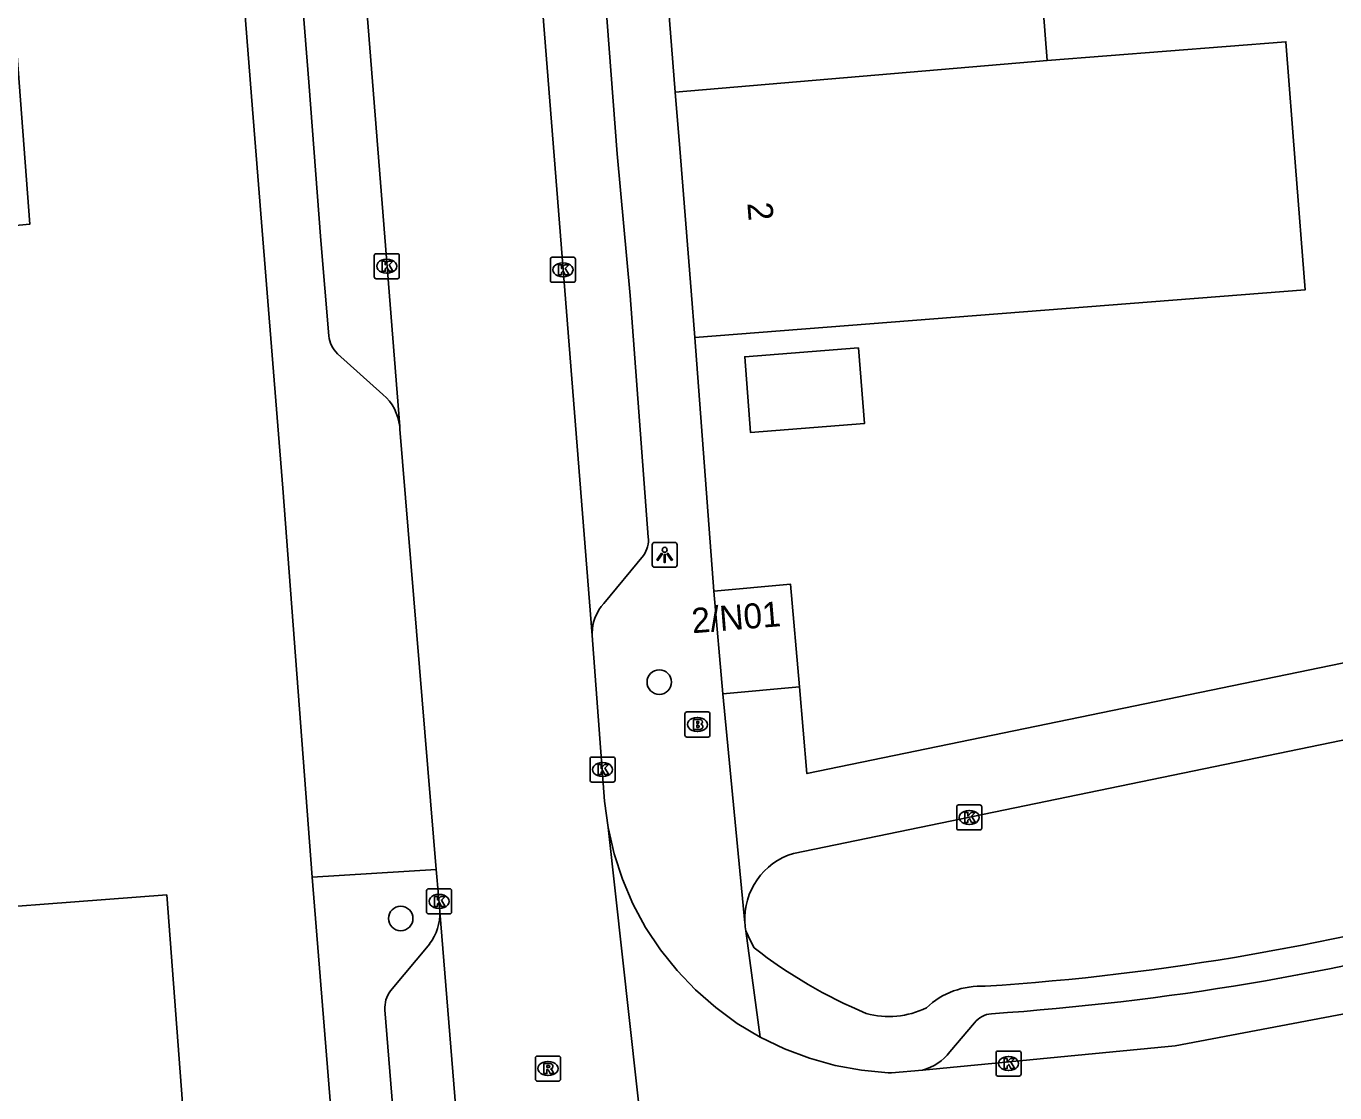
# Model space of a CAD drawing. Extents: x 157793 to 159380, y 380882 to 382313.
# Drawn here: x 158137.7 to 158189.9, y 381083.3 to 381125.9 of the extents above; entities that cross this region are included whole.
import ezdxf

# ---------------------------------------------------------------- set-up
doc = ezdxf.new("R2010")
doc.units = 0
for name, color, linetype in [('IMGEO_Boom', 7, 'Continuous'), ('IMGEO_Brandkraan', 7, 'Continuous'), ('IMGEO_Kolk', 7, 'Continuous'), ('IMGEO_Lichtpunt', 7, 'Continuous'), ('IMGEO_Muur', 7, 'Continuous'), ('IMGEO_Pand', 7, 'Continuous'), ('IMGEO_Pand_nummerreeks', 7, 'Continuous'), ('IMGEO_Rijbaan_lokaal_gesloten', 7, 'Continuous'), ('IMGEO_Rioolput', 7, 'Continuous'), ('IMGEO_Voetpad_open', 7, 'Continuous')]:
    doc.layers.add(name, color=color, linetype=linetype)

msp = doc.modelspace()

# ---------------------------------------------------------------- linework, layer by layer
at = {"layer": 'IMGEO_Boom'}
for centre in [(158162.949, 381099.665), (158152.619, 381090.221)]:
    msp.add_circle(centre, 0.489, dxfattribs=at)
at = {"layer": 'IMGEO_Brandkraan'}
for p, q in [((158163.973, 381097.545), (158163.973, 381098.397)), ((158164.048, 381098.471), (158164.9, 381098.471)), ((158164.461, 381098.251), (158164.486, 381098.251)), ((158164.974, 381098.397), (158164.974, 381097.545)), ((158164.484, 381097.691), (158164.459, 381097.691)), ((158164.9, 381097.471), (158164.048, 381097.471))]:
    msp.add_line(p, q, dxfattribs=at)
for points in [[(158163.973, 381097.545), (158163.973, 381098.397)], [(158164.048, 381098.471), (158164.9, 381098.471)], [(158164.321, 381098.171), (158164.321, 381097.771), (158164.534, 381097.771)], [(158164.552, 381098.171), (158164.321, 381098.171)], [(158164.5, 381098.09), (158164.446, 381098.09), (158164.446, 381098.014)], [(158164.446, 381098.014), (158164.499, 381098.014)], [(158164.974, 381098.397), (158164.974, 381097.545)], [(158164.508, 381097.938), (158164.446, 381097.938), (158164.446, 381097.857)], [(158164.446, 381097.857), (158164.508, 381097.857)], [(158164.9, 381097.471), (158164.048, 381097.471)]]:
    msp.add_lwpolyline(points, dxfattribs=at)
for centre, radius, start, end in [((158164.05, 381098.395), 0.0765, 91.552, 178.448), ((158164.05, 381098.395), 0.0765, 91.552, 178.448), ((158164.501, 381098.052), 0.0379, 267.8285, 90.9355), ((158164.556, 381098.026), 0.145, 59.4692, 91.5367), ((158164.581, 381098.073), 0.0922, 285.5137, 58.1501), ((158164.898, 381098.395), 0.0765, 1.552, 88.448), ((158164.898, 381098.395), 0.0765, 1.552, 88.448), ((158164.05, 381097.547), 0.0765, 181.552, 268.448), ((158164.05, 381097.547), 0.0765, 181.552, 268.448), ((158164.509, 381097.897), 0.0404, 269.8759, 90.5077), ((158164.54, 381098.022), 0.251, 268.6676, 293.5347), ((158164.586, 381097.881), 0.105, 301.3115, 78.989), ((158164.898, 381097.547), 0.0765, 271.552, 358.448), ((158164.898, 381097.547), 0.0765, 271.552, 358.448)]:
    msp.add_arc(centre, radius, start, end, dxfattribs=at)
for centre, major_axis, ratio, start_param, end_param in [((158164.46, 381097.971), (-0.387, 0.002), 0.722429, 4.712389, 7.853982), ((158164.485, 381097.971), (-0.39, 0.002), 0.717154, 1.570796, 4.712389)]:
    msp.add_ellipse(centre, major_axis=major_axis, ratio=ratio, start_param=start_param, end_param=end_param, dxfattribs=at)
at = {"layer": 'IMGEO_Kolk'}
for p, q in [((158151.559, 381115.855), (158151.559, 381116.707)), ((158151.634, 381116.781), (158152.486, 381116.781)), ((158152.047, 381116.561), (158152.072, 381116.561)), ((158152.56, 381116.707), (158152.56, 381115.855)), ((158158.6, 381115.711), (158158.6, 381116.563)), ((158158.675, 381116.637), (158159.527, 381116.637)), ((158159.088, 381116.417), (158159.113, 381116.417)), ((158159.601, 381116.563), (158159.601, 381115.711)), ((158152.486, 381115.781), (158151.634, 381115.781)), ((158152.07, 381116.001), (158152.045, 381116.001)), ((158159.111, 381115.857), (158159.086, 381115.857)), ((158159.527, 381115.637), (158158.675, 381115.637)), ((158160.183, 381095.745), (158160.183, 381096.597)), ((158160.258, 381096.671), (158161.11, 381096.671)), ((158160.671, 381096.451), (158160.696, 381096.451)), ((158161.184, 381096.597), (158161.184, 381095.745)), ((158161.11, 381095.671), (158160.258, 381095.671)), ((158160.694, 381095.891), (158160.669, 381095.891)), ((158174.835, 381093.832), (158174.835, 381094.684)), ((158174.91, 381094.758), (158175.762, 381094.758)), ((158175.323, 381094.538), (158175.348, 381094.538)), ((158175.836, 381094.684), (158175.836, 381093.832)), ((158175.346, 381093.978), (158175.321, 381093.978)), ((158175.762, 381093.758), (158174.91, 381093.758)), ((158153.65, 381090.479), (158153.65, 381091.331)), ((158153.725, 381091.405), (158154.577, 381091.405)), ((158154.651, 381091.331), (158154.651, 381090.479)), ((158154.138, 381091.185), (158154.163, 381091.185)), ((158154.577, 381090.405), (158153.725, 381090.405)), ((158154.161, 381090.625), (158154.136, 381090.625)), ((158176.48, 381084.926), (158177.332, 381084.926)), ((158176.405, 381084), (158176.405, 381084.852)), ((158176.893, 381084.706), (158176.918, 381084.706)), ((158177.406, 381084.852), (158177.406, 381084)), ((158177.332, 381083.926), (158176.48, 381083.926)), ((158176.916, 381084.146), (158176.891, 381084.146))]:
    msp.add_line(p, q, dxfattribs=at)
for points in [[(158151.559, 381115.855), (158151.559, 381116.707)], [(158151.634, 381116.781), (158152.486, 381116.781)], [(158151.88, 381116.481), (158152.003, 381116.481), (158152.003, 381116.33), (158152.133, 381116.481), (158152.297, 381116.481), (158152.151, 381116.33), (158152.304, 381116.081), (158152.152, 381116.081), (158152.067, 381116.245), (158152.003, 381116.178), (158152.003, 381116.081), (158151.88, 381116.081), (158151.88, 381116.481)], [(158152.56, 381116.707), (158152.56, 381115.855)], [(158158.6, 381115.711), (158158.6, 381116.563)], [(158158.675, 381116.637), (158159.527, 381116.637)], [(158158.921, 381116.337), (158159.044, 381116.337), (158159.044, 381116.186), (158159.174, 381116.337), (158159.338, 381116.337), (158159.192, 381116.186), (158159.345, 381115.937), (158159.193, 381115.937), (158159.108, 381116.101), (158159.044, 381116.034), (158159.044, 381115.937), (158158.921, 381115.937), (158158.921, 381116.337)], [(158159.601, 381116.563), (158159.601, 381115.711)], [(158152.486, 381115.781), (158151.634, 381115.781)], [(158159.527, 381115.637), (158158.675, 381115.637)], [(158160.183, 381095.745), (158160.183, 381096.597)], [(158160.258, 381096.671), (158161.11, 381096.671)], [(158161.184, 381096.597), (158161.184, 381095.745)], [(158160.504, 381096.371), (158160.627, 381096.371), (158160.627, 381096.22), (158160.757, 381096.371), (158160.921, 381096.371), (158160.775, 381096.22), (158160.928, 381095.971), (158160.776, 381095.971), (158160.691, 381096.135), (158160.627, 381096.068), (158160.627, 381095.971), (158160.504, 381095.971), (158160.504, 381096.371)], [(158161.11, 381095.671), (158160.258, 381095.671)], [(158174.835, 381093.832), (158174.835, 381094.684)], [(158174.91, 381094.758), (158175.762, 381094.758)], [(158175.156, 381094.458), (158175.279, 381094.458), (158175.279, 381094.307), (158175.409, 381094.458), (158175.573, 381094.458), (158175.427, 381094.307), (158175.58, 381094.058), (158175.428, 381094.058), (158175.343, 381094.222), (158175.279, 381094.155), (158175.279, 381094.058), (158175.156, 381094.058), (158175.156, 381094.458)], [(158175.836, 381094.684), (158175.836, 381093.832)], [(158175.762, 381093.758), (158174.91, 381093.758)], [(158153.65, 381090.479), (158153.65, 381091.331)], [(158153.725, 381091.405), (158154.577, 381091.405)], [(158154.651, 381091.331), (158154.651, 381090.479)], [(158153.971, 381091.105), (158154.094, 381091.105), (158154.094, 381090.954), (158154.224, 381091.105), (158154.388, 381091.105), (158154.242, 381090.954), (158154.395, 381090.705), (158154.243, 381090.705), (158154.158, 381090.869), (158154.094, 381090.802), (158154.094, 381090.705), (158153.971, 381090.705), (158153.971, 381091.105)], [(158154.577, 381090.405), (158153.725, 381090.405)], [(158176.48, 381084.926), (158177.332, 381084.926)], [(158176.405, 381084), (158176.405, 381084.852)], [(158176.726, 381084.626), (158176.849, 381084.626), (158176.849, 381084.475), (158176.979, 381084.626), (158177.143, 381084.626), (158176.997, 381084.475), (158177.15, 381084.226), (158176.998, 381084.226), (158176.913, 381084.39), (158176.849, 381084.323), (158176.849, 381084.226), (158176.726, 381084.226), (158176.726, 381084.626)], [(158177.406, 381084.852), (158177.406, 381084)], [(158177.332, 381083.926), (158176.48, 381083.926)]]:
    msp.add_lwpolyline(points, dxfattribs=at)
for centre, start, end in [((158151.636, 381116.705), 91.552, 178.448), ((158151.636, 381116.705), 91.552, 178.448), ((158152.484, 381116.705), 1.552, 88.448), ((158152.484, 381116.705), 1.552, 88.448), ((158158.677, 381116.561), 91.552, 178.448), ((158158.677, 381116.561), 91.552, 178.448), ((158159.525, 381116.561), 1.552, 88.448), ((158159.525, 381116.561), 1.552, 88.448), ((158151.636, 381115.857), 181.552, 268.448), ((158151.636, 381115.857), 181.552, 268.448), ((158152.484, 381115.857), 271.552, 358.448), ((158152.484, 381115.857), 271.552, 358.448), ((158158.677, 381115.713), 181.552, 268.448), ((158158.677, 381115.713), 181.552, 268.448), ((158159.525, 381115.713), 271.552, 358.448), ((158159.525, 381115.713), 271.552, 358.448), ((158160.26, 381096.595), 91.552, 178.448), ((158160.26, 381096.595), 91.552, 178.448), ((158161.108, 381096.595), 1.552, 88.448), ((158161.108, 381096.595), 1.552, 88.448), ((158160.26, 381095.747), 181.552, 268.448), ((158160.26, 381095.747), 181.552, 268.448), ((158161.108, 381095.747), 271.552, 358.448), ((158161.108, 381095.747), 271.552, 358.448), ((158174.912, 381094.682), 91.552, 178.448), ((158174.912, 381094.682), 91.552, 178.448), ((158175.76, 381094.682), 1.552, 88.448), ((158175.76, 381094.682), 1.552, 88.448), ((158174.912, 381093.834), 181.552, 268.448), ((158174.912, 381093.834), 181.552, 268.448), ((158175.76, 381093.834), 271.552, 358.448), ((158175.76, 381093.834), 271.552, 358.448), ((158153.727, 381091.329), 91.552, 178.448), ((158153.727, 381091.329), 91.552, 178.448), ((158154.575, 381091.329), 1.552, 88.448), ((158154.575, 381091.329), 1.552, 88.448), ((158153.727, 381090.481), 181.552, 268.448), ((158153.727, 381090.481), 181.552, 268.448), ((158154.575, 381090.481), 271.552, 358.448), ((158154.575, 381090.481), 271.552, 358.448), ((158176.482, 381084.85), 91.552, 178.448), ((158176.482, 381084.85), 91.552, 178.448), ((158177.33, 381084.85), 1.552, 88.448), ((158177.33, 381084.85), 1.552, 88.448), ((158176.482, 381084.002), 181.552, 268.448), ((158176.482, 381084.002), 181.552, 268.448), ((158177.33, 381084.002), 271.552, 358.448), ((158177.33, 381084.002), 271.552, 358.448)]:
    msp.add_arc(centre, 0.0765, start, end, dxfattribs=at)
for centre, major_axis, ratio, start_param, end_param in [((158152.046, 381116.281), (-0.387, 0.002), 0.722429, 4.712389, 7.853982), ((158152.071, 381116.281), (-0.39, 0.002), 0.717154, 1.570796, 4.712389), ((158159.087, 381116.137), (-0.387, 0.002), 0.722429, 4.712389, 7.853982), ((158159.112, 381116.137), (-0.39, 0.002), 0.717154, 1.570796, 4.712389), ((158160.67, 381096.171), (-0.387, 0.002), 0.722429, 4.712389, 7.853982), ((158160.695, 381096.171), (-0.39, 0.002), 0.717154, 1.570796, 4.712389), ((158175.322, 381094.258), (-0.387, 0.002), 0.722429, 4.712389, 7.853982), ((158175.347, 381094.258), (-0.39, 0.002), 0.717154, 1.570796, 4.712389), ((158154.137, 381090.905), (-0.387, 0.002), 0.722429, 4.712389, 7.853982), ((158154.162, 381090.905), (-0.39, 0.002), 0.717154, 1.570796, 4.712389), ((158176.892, 381084.426), (-0.387, 0.002), 0.722429, 4.712389, 7.853982), ((158176.917, 381084.426), (-0.39, 0.002), 0.717154, 1.570796, 4.712389)]:
    msp.add_ellipse(centre, major_axis=major_axis, ratio=ratio, start_param=start_param, end_param=end_param, dxfattribs=at)
at = {"layer": 'IMGEO_Lichtpunt'}
for p, q in [((158162.667, 381105.152), (158162.667, 381104.345)), ((158162.667, 381105.152), (158162.667, 381104.345)), ((158163.569, 381105.247), (158162.761, 381105.247)), ((158163.569, 381105.247), (158162.761, 381105.247)), ((158163.663, 381104.345), (158163.663, 381105.152)), ((158163.663, 381104.345), (158163.663, 381105.152)), ((158162.761, 381104.251), (158163.569, 381104.251)), ((158162.761, 381104.251), (158163.569, 381104.251))]:
    msp.add_line(p, q, dxfattribs=at)
for points in [[(158163.041, 381104.816), (158163.08, 381104.788), (158162.892, 381104.526), (158162.854, 381104.553), (158163.041, 381104.816)], [(158163.253, 381104.788), (158163.291, 381104.815), (158163.478, 381104.553), (158163.439, 381104.525), (158163.253, 381104.788)], [(158163.143, 381104.768), (158163.19, 381104.768), (158163.19, 381104.446), (158163.143, 381104.446), (158163.143, 381104.768)]]:
    msp.add_lwpolyline(points, dxfattribs=at)
msp.add_circle((158163.166, 381104.95), 0.0994, dxfattribs=at)
for centre, start, end in [((158162.761, 381105.152), 90, 180), ((158162.761, 381105.152), 90, 180), ((158163.569, 381105.152), 0, 90), ((158163.569, 381105.152), 0, 90), ((158162.761, 381104.345), 180, 270), ((158162.761, 381104.345), 180, 270), ((158163.569, 381104.345), 270, 0), ((158163.569, 381104.345), 270, 360)]:
    msp.add_arc(centre, 0.0946, start, end, dxfattribs=at)
at = {"layer": 'IMGEO_Muur'}
for points in [[(158164.365, 381113.429), (158165.134, 381103.303)], [(158168.549, 381099.472), (158168.846, 381096.013)]]:
    msp.add_lwpolyline(points, dxfattribs=at)
at = {"layer": 'IMGEO_Pand'}
for points in [[(158072.644, 381112.772), (158069.247, 381157.823), (158069.746, 381157.861), (158069.025, 381167.434), (158128.412, 381171.913), (158133.397, 381172.289), (158134.119, 381162.716), (158134.418, 381162.738), (158137.795, 381117.958), (158134.959, 381117.688)], [(158176.899, 381144.348), (158178.452, 381124.502)], [(158163.59, 381123.232), (158163.268, 381127.307), (158162.304, 381139.488), (158162.013, 381143.173)], [(158178.452, 381124.502), (158187.985, 381125.248), (158188.374, 381120.27), (158188.76, 381115.338), (158164.365, 381113.429)], [(158178.452, 381124.502), (158163.59, 381123.232)], [(158164.365, 381113.429), (158164.217, 381115.299), (158163.768, 381120.984), (158163.59, 381123.232)], [(158134.959, 381117.688), (158136.463, 381097.75), (158131.868, 381097.404), (158132.4, 381090.342), (158143.27, 381091.162), (158145.808, 381057.515), (158136.441, 381046.621), (158131.456, 381046.245), (158106.652, 381044.375), (158105.86, 381054.876), (158077.173, 381052.713), (158072.661, 381112.544), (158072.644, 381112.772)], [(158170.909, 381113.021), (158171.146, 381109.99), (158166.599, 381109.634), (158166.362, 381112.665), (158170.909, 381113.021)], [(158165.134, 381103.303), (158168.197, 381103.575), (158168.549, 381099.472)], [(158165.486, 381099.2), (158165.134, 381103.303)], [(158168.549, 381099.472), (158165.486, 381099.2)]]:
    msp.add_lwpolyline(points, dxfattribs=at)
at = {"layer": 'IMGEO_Rijbaan_lokaal_gesloten'}
for points in [[(158160.265, 381101.527), (158150.099, 381229.806), (158149.14, 381242.015)], [(158144.104, 381216.957), (158152.577, 381109.874)], [(158152.577, 381109.874), (158152.586, 381109.766), (158154.041, 381092.18)], [(158160.906, 381093.85), (158160.761, 381094.91), (158160.265, 381101.527)], [(158163.463, 381070.73), (158160.906, 381093.85)], [(158166.985, 381085.48), (158166.068, 381086.03), (158165.204, 381086.659), (158164.399, 381087.364), (158163.66, 381088.137), (158162.994, 381088.974), (158162.405, 381089.866), (158161.898, 381090.808), (158161.477, 381091.791), (158161.145, 381092.808), (158160.906, 381093.85)], [(158154.041, 381092.18), (158154.127, 381091.136), (158154.165, 381090.674), (158154.179, 381090.5)], [(158154.179, 381090.5), (158156.578, 381060.941)], [(158200.484, 381088.849), (158193.766, 381087.058), (158183.564, 381085.139), (158173.465, 381084.163)], [(158173.465, 381084.163), (158172.225, 381084.05), (158172.095, 381084.056), (158171.03, 381084.155), (158169.979, 381084.349), (158168.948, 381084.636), (158167.948, 381085.014), (158166.985, 381085.48)]]:
    msp.add_lwpolyline(points, dxfattribs=at)
at = {"layer": 'IMGEO_Rioolput'}
for p, q in [((158158.001, 381083.8), (158158.001, 381084.652)), ((158158.076, 381084.726), (158158.928, 381084.726)), ((158158.489, 381084.506), (158158.514, 381084.506)), ((158159.002, 381084.652), (158159.002, 381083.8)), ((158158.512, 381083.946), (158158.487, 381083.946)), ((158158.928, 381083.726), (158158.076, 381083.726))]:
    msp.add_line(p, q, dxfattribs=at)
for points in [[(158158.001, 381083.8), (158158.001, 381084.652)], [(158158.076, 381084.726), (158158.928, 381084.726)], [(158158.59, 381084.424), (158158.338, 381084.426), (158158.338, 381084.026)], [(158159.002, 381084.652), (158159.002, 381083.8)], [(158158.338, 381084.026), (158158.462, 381084.026), (158158.462, 381084.188), (158158.473, 381084.188)], [(158158.516, 381084.345), (158158.462, 381084.345), (158158.462, 381084.264)], [(158158.462, 381084.264), (158158.514, 381084.264)], [(158158.52, 381084.159), (158158.591, 381084.026), (158158.731, 381084.026), (158158.666, 381084.152)], [(158158.928, 381083.726), (158158.076, 381083.726)]]:
    msp.add_lwpolyline(points, dxfattribs=at)
for centre, radius, start, end in [((158158.078, 381084.65), 0.0765, 91.552, 178.448), ((158158.078, 381084.65), 0.0765, 91.552, 178.448), ((158158.589, 381084.314), 0.109, 350.3612, 89.416), ((158158.926, 381084.65), 0.0765, 1.552, 88.448), ((158158.926, 381084.65), 0.0765, 1.552, 88.448), ((158158.472, 381084.135), 0.0533, 26.0293, 88.6989), ((158158.498, 381084.453), 0.19, 274.7715, 282.9687), ((158158.522, 381084.249), 0.0964, 77.0061, 93.1865), ((158158.536, 381084.306), 0.0378, 276.6634, 79.6772), ((158158.587, 381084.314), 0.112, 277.5842, 350.9817), ((158158.571, 381084.099), 0.108, 29.5134, 73.7905), ((158158.078, 381083.802), 0.0765, 181.552, 268.448), ((158158.078, 381083.802), 0.0765, 181.552, 268.448), ((158158.926, 381083.802), 0.0765, 271.552, 358.448), ((158158.926, 381083.802), 0.0765, 271.552, 358.448)]:
    msp.add_arc(centre, radius, start, end, dxfattribs=at)
for centre, major_axis, ratio, start_param, end_param in [((158158.488, 381084.226), (-0.387, 0.002), 0.722429, 4.712389, 7.853982), ((158158.513, 381084.226), (-0.39, 0.002), 0.717154, 1.570796, 4.712389)]:
    msp.add_ellipse(centre, major_axis=major_axis, ratio=ratio, start_param=start_param, end_param=end_param, dxfattribs=at)
at = {"layer": 'IMGEO_Voetpad_open'}
for points in [[(158144.53, 381179.608), (158146.968, 381148.6), (158148.941, 381123.639), (158149.426, 381117.309), (158149.748, 381113.496)], [(158149.076, 381091.874), (158147.913, 381107.409), (158147.053, 381118.043), (158146.695, 381122.56), (158144.586, 381149.315), (158143.395, 381163.444), (158142.048, 381179.413)], [(158160.265, 381101.527), (158160.265, 381101.625), (158160.275, 381101.786), (158160.301, 381101.947), (158160.34, 381102.104), (158160.394, 381102.257), (158160.461, 381102.405), (158160.54, 381102.546), (158160.632, 381102.679), (158160.736, 381102.804), (158162.319, 381104.726), (158162.371, 381104.807), (158162.416, 381104.893), (158162.453, 381104.983), (158162.482, 381105.075), (158162.502, 381105.17), (158162.514, 381105.266), (158162.517, 381105.362), (158162.512, 381105.454), (158161.789, 381115.107), (158161.263, 381120.769), (158160.781, 381127.099)], [(158164.365, 381113.429), (158165.134, 381103.303)], [(158150.094, 381112.783), (158151.909, 381111.156)], [(158168.549, 381099.472), (158168.846, 381096.013), (158217.702, 381106.076)], [(158168.317, 381092.823), (158215.438, 381102.536)], [(158166.373, 381090.041), (158165.486, 381099.2)], [(158149.076, 381091.874), (158154.041, 381092.18)], [(158150.213, 381054.177), (158151.122, 381054.959), (158151.977, 381055.822), (158149.076, 381091.874)], [(158166.985, 381085.48), (158166.411, 381089.724)], [(158166.743, 381089.047), (158166.588, 381089.334), (158166.411, 381089.724)], [(158153.775, 381089.211), (158152.206, 381087.328)], [(158151.986, 381086.576), (158153.767, 381064.564)], [(158174.563, 381084.896), (158175.547, 381086.058)]]:
    msp.add_lwpolyline(points, dxfattribs=at)
for centre, radius, start, end in [((158150.836, 381113.584), 1.092, 184.5999, 227.1723), ((158150.617, 381109.668), 1.971, 6.0103, 49.0342), ((158169.095, 381090.209), 2.727, 106.5707, 183.5393), ((158169.319, 381188.414), 101.121, 273.77475, 285.8971), ((158152.144, 381090.43), 2.036, 323.2255, 1.9703), ((158168.908, 381090.184), 2.539, 183.2304, 190.4408), ((158168.855, 381193.417), 107.257, 273.93813, 285.03827), ((158178.54, 381104.077), 19.106, 231.8718, 247.4738), ((158153.116, 381086.654), 1.132, 143.4541, 183.9319), ((158175.791, 381084.364), 3.153, 86.6352, 133.4872), ((158172.125, 381089.705), 3.4, 254.5609, 296.099), ((158176.283, 381085.479), 0.936, 93.7732, 141.7789), ((158172.963, 381086.104), 2.004, 284.4993, 322.953)]:
    msp.add_arc(centre, radius, start, end, dxfattribs=at)

# ---------------------------------------------------------------- texts
at = {"layer": 'IMGEO_Pand_nummerreeks'}
for s, rotation, p in [('2', 274.5203, (158166.467, 381118.806)), ('2/N01', 4.6355, (158164.279, 381101.614))]:
    msp.add_text(s, height=1, rotation=rotation, dxfattribs=at).set_placement(p)

doc.saveas('drawing.dxf')
